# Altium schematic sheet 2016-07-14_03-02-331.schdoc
size 424 x 220 mm; SheetNumber: 1; SheetTotal: 1
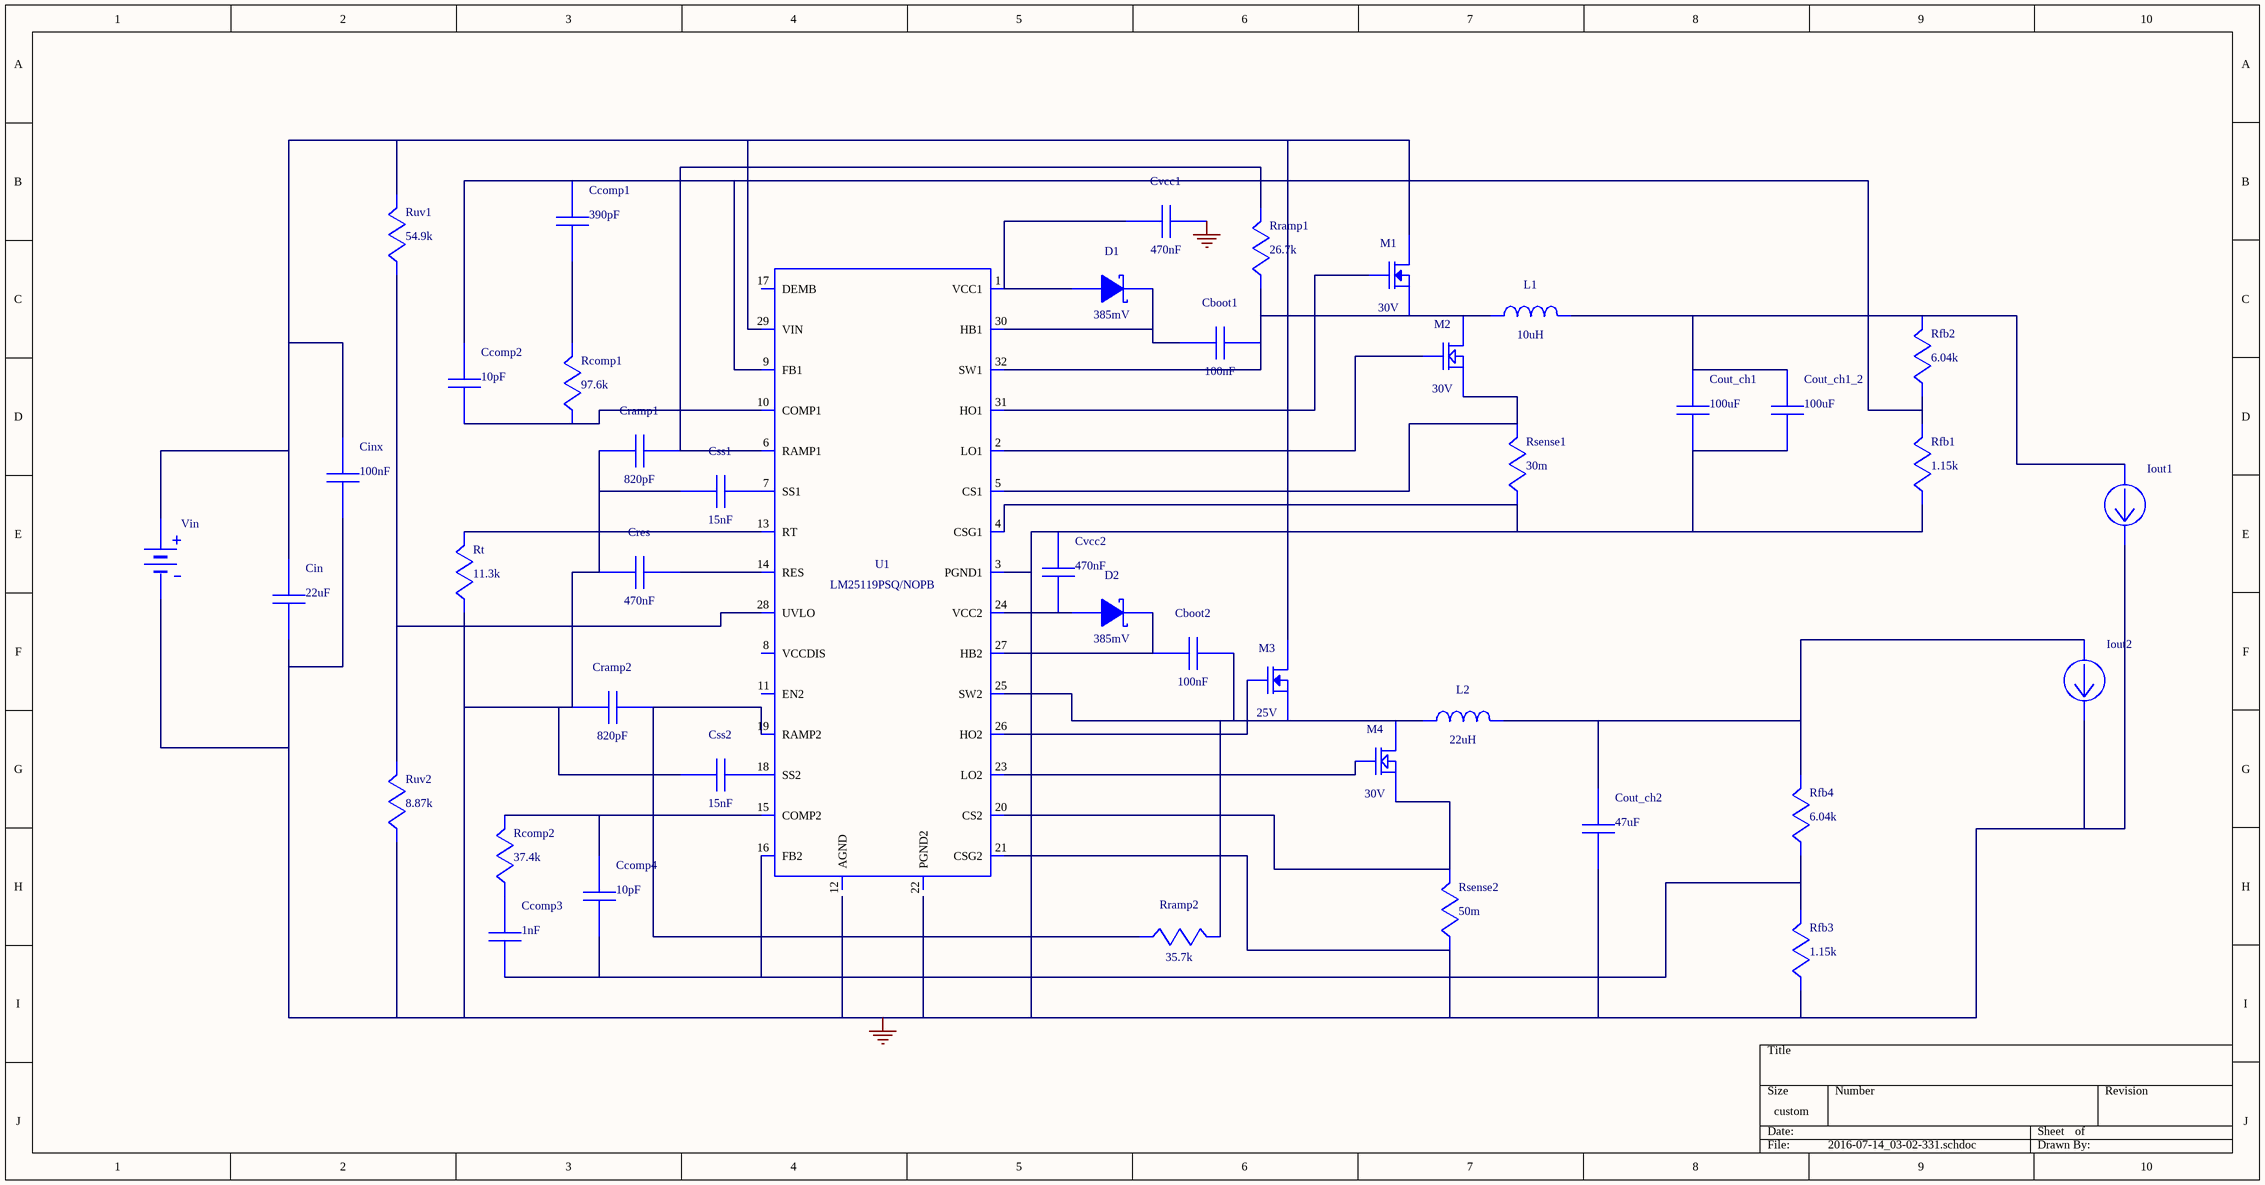
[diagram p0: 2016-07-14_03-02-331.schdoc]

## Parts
Cboot1  value 100nF  (hidden comment: GRM155R61A104KA01D)
Cboot2  value 100nF  (hidden comment: GRM155R61A104KA01D)
Ccomp1  value 390pF  (hidden comment: CC0805KRX7R9BB391)
Ccomp2  value 10pF  (hidden comment: C0805C100K5GACTU)
Ccomp3  value 1nF  (hidden comment: CL21C102JBCNFNC)
Ccomp4  value 10pF  (hidden comment: C0805C100K5GACTU)
Cin  value 22uF  (hidden comment: GRM32ER61E226KE15L)
Cinx  value 100nF  (hidden comment: 08053C104KAT2A)
Cout_ch1  value 100uF  (hidden comment: GRM31CR60J107ME39L)
Cout_ch1_2  value 100uF  (hidden comment: GRM31CR60J107ME39L)
Cout_ch2  value 47uF  (hidden comment: GRM31CR61A476KE15L)
Cramp1  value 820pF  (hidden comment: CC0805KRX7R9BB821)
Cramp2  value 820pF  (hidden comment: CC0805KRX7R9BB821)
Cres  value 470nF  (hidden comment: GRM155C80J474KE19D)
Css1  value 15nF  (hidden comment: CC0805KRX7R9BB153)
Css2  value 15nF  (hidden comment: CC0805KRX7R9BB153)
Cvcc1  value 470nF  (hidden comment: GRM155R61A474KE15D)
Cvcc2  value 470nF  (hidden comment: GRM155R61A474KE15D)
D1  value 385mV  (hidden comment: MBR0520LT1G)
D2  value 385mV  (hidden comment: MBR0520LT1G)
Iout1  WB_CURRENT_LOAD  (value not drawn)
Iout2  WB_CURRENT_LOAD  (value not drawn)
L1  value 10uH  (hidden comment: VLP8040T-100M)
L2  value 22uH  (hidden comment: SRN6045-220M)
M1  value 30V  (hidden comment: CSD17308Q3)
M2  value 30V  (hidden comment: CSD17578Q3A)
M3  value 25V  (hidden comment: CSD16411Q3)
M4  value 30V  (hidden comment: CSD17579Q3A)
Rcomp1  value 97.6k  (hidden comment: CRCW040297K6FKED)
Rcomp2  value 37.4k  (hidden comment: CRCW040237K4FKED)
Rfb1  value 1.15k  (hidden comment: CRCW04021K15FKED)
Rfb2  value 6.04k  (hidden comment: CRCW04026K04FKED)
Rfb3  value 1.15k  (hidden comment: CRCW04021K15FKED)
Rfb4  value 6.04k  (hidden comment: CRCW04026K04FKED)
Rramp1  value 26.7k  (hidden comment: CRCW040226K7FKED)
Rramp2  value 35.7k  (hidden comment: CRCW040235K7FKED)
Rsense1  value 30m  (hidden comment: CSR1206FK30L0)
Rsense2  value 50m  (hidden comment: ERJ-L03KF50MV)
Rt  value 11.3k  (hidden comment: CRCW040211K3FKED)
Ruv1  value 54.9k  (hidden comment: CRCW040254K9FKED)
Ruv2  value 8.87k  (hidden comment: CRCW04028K87FKED)
U1  LM25119PSQ/NOPB
Vin  WB_BATTERY  (value not drawn)

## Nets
0: Cin.2 Cinx.2 Cout_ch1.2 Cout_ch1_2.2 Cout_ch2.2 Cramp1.2 Cramp2.2 Cres.2 Css1.2 Css2.2 Cvcc1.2 Cvcc2.2 Iout1.2(-) Iout2.2(-) Rfb1.2 Rfb3.2 Rsense1.2 Rsense2.2 Rt.2 Ruv2.2 U1.3(PGND1) U1.4(CSG1) U1.21(CSG2) U1.33(EP) Vin.2(-)
NetCboot1_1: Cboot1.1 L1.1 M1.1(Source) M1.2(Source) M1.3(Source) M2.5(Drain) M2.6(Drain) M2.7(Drain) M2.8(Drain) M2.9(Drain) Rramp1.2 U1.32(SW1)
NetCboot1_2: Cboot1.2 D1.1(K) U1.30(HB1)
NetCboot2_1: Cboot2.1 L2.1 M3.1(Source) M3.2(Source) M3.3(Source) M4.5(Drain) M4.6(Drain) M4.7(Drain) M4.8(Drain) M4.9(Drain) Rramp2.1 U1.25(SW2)
NetCboot2_2: Cboot2.2 D2.1(K) U1.27(HB2)
NetCcomp1_1: Ccomp1.1 Rcomp1.1
NetCcomp1_2: Ccomp1.2 Ccomp2.2 Rfb1.1 Rfb2.2 U1.9(FB1)
NetCcomp2_1: Ccomp2.1 Rcomp1.2 U1.10(COMP1)
NetCcomp3_1: Ccomp3.1 Rcomp2.2
NetCcomp3_2: Ccomp3.2 Ccomp4.2 Rfb3.1 Rfb4.2 U1.16(FB2)
NetCcomp4_1: Ccomp4.1 Rcomp2.1 U1.15(COMP2)
NetCin_1: Cin.1 Cinx.1 M1.5(Drain) M1.6(Drain) M1.7(Drain) M1.8(Drain) M1.9(Drain) M3.5(Drain) M3.6(Drain) M3.7(Drain) M3.8(Drain) M3.9(Drain) Ruv1.1 U1.29(VIN) Vin.1(+)
NetCout_ch1_1: Cout_ch1.1 Cout_ch1_2.1 Iout1.1(+) L1.2 Rfb2.1
NetCout_ch2_1: Cout_ch2.1 Iout2.1(+) L2.2 Rfb4.1
NetCramp1_1: Cramp1.1 Rramp1.1 U1.6(RAMP1)
NetCramp2_1: Cramp2.1 Rramp2.2 U1.19(RAMP2)
NetCres_1: Cres.1 U1.14(RES)
NetCss1_1: Css1.1 U1.7(SS1)
NetCss2_1: Css2.1 U1.18(SS2)
NetCvcc1_1: Cvcc1.1 D1.2(A) U1.1(VCC1)
NetCvcc2_1: Cvcc2.1 D2.2(A) U1.24(VCC2)
NetM1_4: M1.4(Gate) U1.31(HO1)
NetM2_1: M2.1(Source) M2.2(Source) M2.3(Source) Rsense1.1 U1.5(CS1)
NetM2_4: M2.4(Gate) U1.2(LO1)
NetM3_4: M3.4(Gate) U1.26(HO2)
NetM4_1: M4.1(Source) M4.2(Source) M4.3(Source) Rsense2.1 U1.20(CS2)
NetM4_4: M4.4(Gate) U1.23(LO2)
NetRt_1: Rt.1 U1.13(RT)
NetRuv1_2: Ruv1.2 Ruv2.1 U1.28(UVLO)

Not connected (* = marked no-connect by the designer): U1 8(VCCDIS) 11(EN2) 12(AGND) 17(DEMB) 22(PGND2)

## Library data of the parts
Cboot1 Cboot2 = GRM155R61A104KA01D: GRM155R61A104KA0; Manufacturer Name: MuRata
Ccomp1 = CC0805KRX7R9BB391: CC0805KRX7R9BB39; Manufacturer Name: Yageo America
Ccomp2 Ccomp4 = C0805C100K5GACTU: Manufacturer Name: Kemet
Ccomp3 = CL21C102JBCNFNC: Manufacturer Name: Samsung Electro-Mechanics
Cin = GRM32ER61E226KE15L: GRM32ER61E226KE1; Manufacturer Name: MuRata
Cinx = 08053C104KAT2A: Manufacturer Name: AVX
Cout_ch1 Cout_ch1_2 = GRM31CR60J107ME39L: GRM31CR60J107ME3; Manufacturer Name: MuRata
Cout_ch2 = GRM31CR61A476KE15L: GRM31CR61A476KE1; Manufacturer Name: MuRata
Cramp1 Cramp2 = CC0805KRX7R9BB821: CC0805KRX7R9BB82; Manufacturer Name: Yageo America
Cres = GRM155C80J474KE19D: GRM155C80J474KE1; Manufacturer Name: MuRata
Css1 Css2 = CC0805KRX7R9BB153: CC0805KRX7R9BB15; Manufacturer Name: Yageo America
Cvcc1 Cvcc2 = GRM155R61A474KE15D: GRM155R61A474KE1; Manufacturer Name: MuRata
D1 D2 = MBR0520LT1G: Manufacturer Name: ON Semiconductor
L1 = VLP8040T-100M: Unknown; Manufacturer Name: TDK
L2 = SRN6045-220M: Manufacturer Name: Bourns
M1 = CSD17308Q3: Manufacturer Name: Texas Instruments
M2 = CSD17578Q3A: Manufacturer Name: Texas Instruments
M3 = CSD16411Q3: Manufacturer Name: Texas Instruments
M4 = CSD17579Q3A: Manufacturer Name: Texas Instruments
Rcomp1 = CRCW040297K6FKED: Manufacturer Name: Vishay-Dale
Rcomp2 = CRCW040237K4FKED: Manufacturer Name: Vishay-Dale
Rfb1 Rfb3 = CRCW04021K15FKED: Manufacturer Name: Vishay-Dale
Rfb2 Rfb4 = CRCW04026K04FKED: Manufacturer Name: Vishay-Dale
Rramp1 = CRCW040226K7FKED: Manufacturer Name: Vishay-Dale
Rramp2 = CRCW040235K7FKED: Manufacturer Name: Vishay-Dale
Rsense1 = CSR1206FK30L0: Manufacturer Name: Stackpole Electronics Inc
Rsense2 = ERJ-L03KF50MV: Manufacturer Name: Panasonic
Rt = CRCW040211K3FKED: Manufacturer Name: Vishay-Dale
Ruv1 = CRCW040254K9FKED: Manufacturer Name: Vishay-Dale
Ruv2 = CRCW04028K87FKED: Manufacturer Name: Vishay-Dale
U1 = LM25119PSQ/NOPB: Manufacturer Name: Texas Instruments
